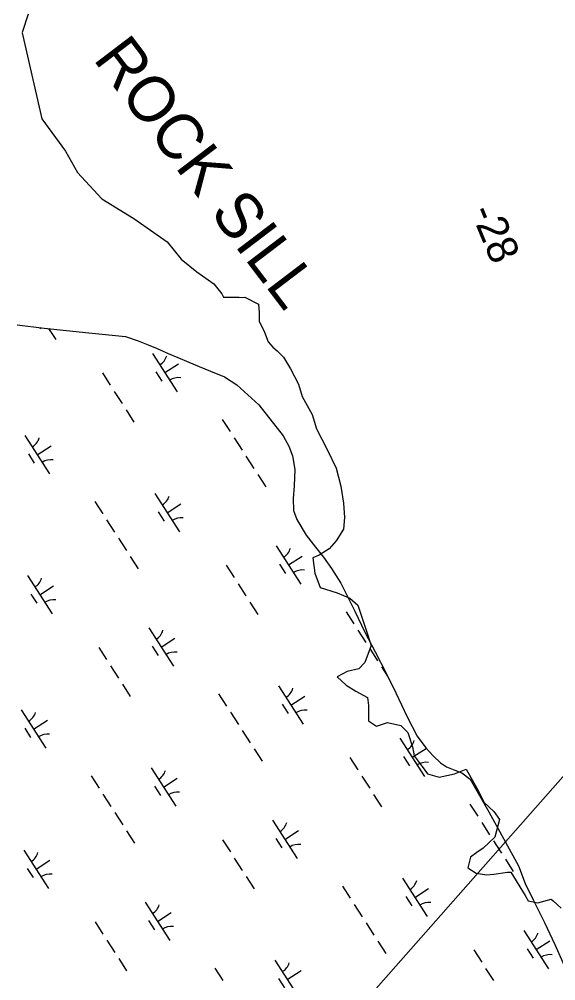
# Model space of a CAD drawing. Extents: x 3937982 to 3958556, y 219448 to 241894.
# Drawn here: x 3948736 to 3949325, y 226625 to 227680 of the extents above; entities that cross this region are included whole.
import ezdxf

# ---------------------------------------------------------------- set-up
doc = ezdxf.new("R2010")
doc.units = 0
for name, color, linetype in [('V-RIVR-EDGE', 7, 'Continuous'), ('V-RIVR-RANG', 7, 'Continuous'), ('V-RRAP-SILL-IDEN', 7, 'Continuous'), ('V-UTIL-LINE', 7, 'Continuous'), ('V-WETL-SWMP', 7, 'Continuous')]:
    doc.layers.add(name, color=color, linetype=linetype)

msp = doc.modelspace()

# ---------------------------------------------------------------- linework, layer by layer
at = {"layer": 'V-RIVR-EDGE'}
for points in [[(3948746.134, 227686.005), (3948739.531, 227665.724)], [(3948739.735, 227665.535), (3948761.326, 227571.012), (3948787.236, 227535.506), (3948800.191, 227511.995), (3948827.06, 227483.207), (3948862.087, 227461.615), (3948898.552, 227436.185), (3948913.906, 227416.993), (3948931.179, 227403.078), (3948949.892, 227390.124), (3948958.529, 227379.088), (3948960.448, 227375.249), (3948977.721, 227375.249)], [(3948976.723, 227375.027), (3948983.994, 227375.41), (3948998.738, 227367.546), (3948999.721, 227358.7), (3948999.721, 227348.871), (3949005.618, 227337.077), (3949009.55, 227326.265), (3949014.464, 227320.367), (3949019.379, 227316.436), (3949026.259, 227309.556), (3949034.122, 227296.778), (3949042.968, 227280.069), (3949046.9, 227266.308), (3949057.712, 227246.65), (3949062.626, 227230.924), (3949074.421, 227208.317), (3949084.25, 227187.676), (3949089.164, 227168.019), (3949092.113, 227149.344), (3949093.096, 227133.617), (3949092.113, 227120.84), (3949084.25, 227108.062), (3949076.387, 227099.216), (3949065.575, 227092.336), (3949058.695, 227089.387), (3949060.66, 227072.678), (3949066.558, 227056.951), (3949085.233, 227051.054), (3949098.993, 227045.157), (3949107.839, 227037.293), (3949117.668, 227007.807), (3949122.583, 226993.063), (3949115.703, 226974.388), (3949108.822, 226967.508), (3949096.045, 226964.559), (3949085.233, 226958.662), (3949095.062, 226949.816), (3949105.874, 226942.935), (3949118.651, 226936.055), (3949119.634, 226927.209), (3949119.634, 226923.277), (3949119.634, 226910.5), (3949128.48, 226904.602), (3949140.275, 226908.534), (3949155.018, 226905.585), (3949162.882, 226897.722), (3949167.796, 226881.996), (3949169.762, 226872.167), (3949178.608, 226860.372), (3949184.505, 226852.509), (3949197.283, 226848.577), (3949213.992, 226852.509), (3949226.77, 226857.423), (3949238.564, 226836.783), (3949246.428, 226821.056), (3949257.24, 226811.227), (3949263.137, 226802.381), (3949258.222, 226782.723), (3949245.445, 226770.929), (3949238.564, 226766.014), (3949231.684, 226761.1), (3949228.736, 226749.305), (3949237.582, 226743.408), (3949249.376, 226741.442), (3949257.24, 226742.425), (3949271.983, 226744.39), (3949275.915, 226744.39), (3949291.641, 226718.835), (3949294.59, 226712.938), (3949305.401, 226710.972), (3949320.145, 226714.904), (3949322.111, 226712.938), (3949330.957, 226705.075)]]:
    msp.add_lwpolyline(points, dxfattribs=at)
at = {"layer": 'V-UTIL-LINE'}
msp.add_line((3950898.169, 228625.327), (3949080.141, 226562.604), dxfattribs=at)
at = {"layer": 'V-WETL-SWMP'}
for p, q in [((3948734.219, 227345.065), (3948763.775, 227341.5)), ((3948758.696, 227342.113), (3948759.637, 227340.65)), ((3948763.775, 227341.5), (3948812.578, 227336.27)), ((3948768.598, 227340.983), (3948776.408, 227328.85)), ((3948812.578, 227336.27), (3948853.018, 227332.363)), ((3948853.018, 227332.363), (3948867.033, 227327.371)), ((3948867.033, 227327.371), (3948877.74, 227323.141)), ((3948877.74, 227323.141), (3948887.864, 227318.909)), ((3948887.864, 227318.909), (3948899.936, 227313.714)), ((3948882.475, 227313.595), (3948909.537, 227271.551)), ((3948899.936, 227313.714), (3948910.451, 227309.095)), ((3948910.451, 227309.095), (3948922.523, 227303.9)), ((3948896.006, 227292.573), (3948911.142, 227302.315)), ((3948922.523, 227303.9), (3948933.815, 227299.285)), ((3948933.815, 227299.285), (3948946.275, 227294.091)), ((3948946.275, 227294.091), (3948961.461, 227287.938)), ((3948827.609, 227292.197), (3948836.269, 227278.744)), ((3948886.271, 227293.442), (3948892.766, 227283.352)), ((3948961.461, 227287.938), (3948975.297, 227279.058)), ((3948975.297, 227279.058), (3948999.101, 227257.394)), ((3948840.599, 227272.017), (3948849.259, 227258.563)), ((3948853.589, 227251.836), (3948862.249, 227238.382)), ((3948999.101, 227257.394), (3949025.874, 227223.111)), ((3948959.176, 227241.309), (3948967.836, 227227.856)), ((3948742.608, 227223.565), (3948769.67, 227181.522)), ((3948972.166, 227221.129), (3948980.826, 227207.675)), ((3949025.874, 227223.111), (3949032.141, 227212.06)), ((3948756.139, 227202.543), (3948771.275, 227212.286)), ((3949032.141, 227212.06), (3949036.074, 227201.388)), ((3948746.404, 227203.413), (3948752.899, 227193.322)), ((3948985.156, 227200.948), (3948993.816, 227187.494)), ((3949036.074, 227201.388), (3949038.665, 227186.435)), ((3948998.146, 227180.767), (3949006.806, 227167.313)), ((3949038.665, 227186.435), (3949038.16, 227168.553)), ((3949038.16, 227168.553), (3949037.054, 227154.555)), ((3948885.174, 227159.875), (3948912.236, 227117.832)), ((3948819.309, 227151.28), (3948827.969, 227137.826)), ((3948898.705, 227138.853), (3948913.84, 227148.596)), ((3949037.054, 227154.555), (3949037.305, 227141.341)), ((3948888.97, 227139.722), (3948895.465, 227129.632)), ((3949037.305, 227141.341), (3949040.846, 227131.445)), ((3948832.299, 227131.099), (3948840.959, 227117.645)), ((3949040.846, 227131.445), (3949051.221, 227114.193)), ((3948845.289, 227110.918), (3948853.948, 227097.465)), ((3949051.221, 227114.193), (3949061.578, 227101.022)), ((3949018.303, 227102.576), (3949045.365, 227060.533)), ((3949061.578, 227101.022), (3949070.371, 227090.177)), ((3948858.278, 227090.738), (3948866.938, 227077.284)), ((3949031.834, 227081.555), (3949046.97, 227091.297)), ((3949070.371, 227090.177), (3949078.976, 227077.776)), ((3948963.437, 227081.179), (3948972.097, 227067.725)), ((3949022.099, 227082.424), (3949028.594, 227072.333)), ((3949078.976, 227077.776), (3949089.152, 227061.495)), ((3948745.306, 227069.845), (3948772.369, 227027.802)), ((3948758.838, 227048.824), (3948773.973, 227058.566)), ((3948976.427, 227060.998), (3948985.087, 227047.545)), ((3949089.152, 227061.495), (3949104.443, 227030.855)), ((3948749.102, 227049.693), (3948755.597, 227039.603)), ((3948989.417, 227040.818), (3948998.077, 227027.364)), ((3949095.004, 227030.291), (3949103.664, 227016.837)), ((3949104.443, 227030.855), (3949115.621, 227007.776)), ((3948878.436, 227012.547), (3948905.498, 226970.504)), ((3949107.994, 227010.11), (3949116.654, 226996.657)), ((3948891.967, 226991.525), (3948907.102, 227001.268)), ((3949115.621, 227007.776), (3949126.791, 226986.252)), ((3948823.57, 226991.15), (3948832.23, 226977.696)), ((3948882.232, 226992.394), (3948888.727, 226982.304)), ((3949120.984, 226989.93), (3949129.644, 226976.476)), ((3949126.791, 226986.252), (3949138.942, 226962.789)), ((3948836.56, 226970.969), (3948845.219, 226957.515)), ((3949133.974, 226969.749), (3949140.524, 226959.572)), ((3949138.942, 226962.789), (3949149.53, 226941.262)), ((3948849.549, 226950.788), (3948858.209, 226937.334)), ((3949021.002, 226948.857), (3949048.064, 226906.813)), ((3948955.137, 226940.262), (3948963.797, 226926.808)), ((3949034.533, 226927.835), (3949049.668, 226937.577)), ((3949149.53, 226941.262), (3949161.887, 226915.079)), ((3949024.798, 226928.704), (3949031.293, 226918.614)), ((3948738.568, 226922.517), (3948765.631, 226880.474)), ((3948968.126, 226920.081), (3948976.786, 226906.627)), ((3949161.887, 226915.079), (3949172.863, 226893.554)), ((3948752.1, 226901.496), (3948767.235, 226911.238)), ((3948742.364, 226902.365), (3948748.859, 226892.274)), ((3948981.116, 226899.9), (3948989.776, 226886.446)), ((3949172.863, 226893.554), (3949182.635, 226880.77)), ((3949154.131, 226891.558), (3949181.193, 226849.515)), ((3948994.106, 226879.719), (3949002.766, 226866.266)), ((3949167.662, 226870.536), (3949182.798, 226880.279)), ((3949182.635, 226880.77), (3949190.446, 226872.252)), ((3949190.446, 226872.252), (3949198.643, 226864.319)), ((3949099.265, 226870.161), (3949107.925, 226856.707)), ((3949157.927, 226871.406), (3949164.422, 226861.315)), ((3949198.643, 226864.319), (3949205.074, 226860.072)), ((3948881.134, 226858.827), (3948908.197, 226816.784)), ((3949205.074, 226860.072), (3949214.224, 226856.419)), ((3949214.224, 226856.419), (3949222.011, 226853.537)), ((3949222.011, 226853.537), (3949230.981, 226846.579)), ((3948815.269, 226850.232), (3948823.929, 226836.778)), ((3948894.665, 226837.805), (3948909.801, 226847.548)), ((3949112.255, 226849.98), (3949120.915, 226836.526)), ((3949230.981, 226846.579), (3949251.737, 226810.521)), ((3948828.259, 226830.051), (3948836.919, 226816.598)), ((3948884.93, 226838.675), (3948891.425, 226828.584)), ((3949125.245, 226829.799), (3949133.904, 226816.346)), ((3949230.832, 226819.273), (3949239.492, 226805.819)), ((3948841.249, 226809.871), (3948849.909, 226796.417)), ((3949251.737, 226810.521), (3949284.02, 226751.303)), ((3949014.264, 226801.528), (3949041.326, 226759.485)), ((3949243.822, 226799.092), (3949252.482, 226785.638)), ((3948854.239, 226789.69), (3948862.899, 226776.236)), ((3949027.795, 226780.507), (3949042.93, 226790.249)), ((3948959.397, 226780.131), (3948968.057, 226766.678)), ((3949018.06, 226781.376), (3949024.554, 226771.286)), ((3949256.811, 226778.911), (3949265.471, 226765.458)), ((3948741.267, 226768.798), (3948768.329, 226726.754)), ((3948754.798, 226747.776), (3948769.934, 226757.518)), ((3948972.387, 226759.951), (3948981.047, 226746.497)), ((3949269.801, 226758.731), (3949278.461, 226745.277)), ((3948745.063, 226748.645), (3948751.558, 226738.555)), ((3949284.02, 226751.303), (3949291.344, 226732.116)), ((3948985.377, 226739.77), (3948994.037, 226726.316)), ((3949156.829, 226737.838), (3949183.892, 226695.795)), ((3949090.964, 226729.243), (3949099.624, 226715.79)), ((3949170.361, 226716.817), (3949185.496, 226726.559)), ((3949291.344, 226732.116), (3949300.726, 226713.284)), ((3949160.625, 226717.686), (3949167.12, 226707.596)), ((3948874.396, 226711.499), (3948901.459, 226669.456)), ((3949103.954, 226709.063), (3949112.614, 226695.609)), ((3949300.726, 226713.284), (3949312.542, 226689.316)), ((3948887.927, 226690.477), (3948903.063, 226700.22)), ((3948819.53, 226690.102), (3948828.19, 226676.648)), ((3948878.192, 226691.347), (3948884.687, 226681.256)), ((3949116.944, 226688.882), (3949125.604, 226675.428)), ((3949312.542, 226689.316), (3949324.017, 226665.002)), ((3949289.959, 226680.54), (3949317.021, 226638.497)), ((3948832.52, 226669.921), (3948841.18, 226656.467)), ((3949129.934, 226668.701), (3949138.594, 226655.247)), ((3949303.49, 226659.518), (3949318.625, 226669.261)), ((3949324.017, 226665.002), (3949334.11, 226642.054)), ((3949235.093, 226659.143), (3949243.753, 226645.689)), ((3949293.755, 226660.387), (3949300.25, 226650.297)), ((3948845.51, 226649.74), (3948854.17, 226636.287)), ((3949016.962, 226647.809), (3949044.024, 226605.766)), ((3948951.097, 226639.214), (3948959.757, 226625.76)), ((3949030.493, 226626.787), (3949045.629, 226636.53)), ((3949248.082, 226638.962), (3949256.742, 226625.508)), ((3949020.758, 226627.656), (3949027.253, 226617.566))]:
    msp.add_line(p, q, dxfattribs=at)
for centre, start, end in [((3948881.256, 227315.927), 301.99668, 343.540338), ((3948911.156, 227269.476), 81.996677, 123.540335), ((3948741.389, 227225.898), 301.99668, 343.540338), ((3948771.289, 227179.446), 81.996677, 123.540335), ((3948883.954, 227162.208), 301.99668, 343.540338), ((3948913.855, 227115.756), 81.996677, 123.540335), ((3949017.084, 227104.909), 301.99668, 343.540338), ((3949046.984, 227058.457), 81.996677, 123.540335), ((3948744.087, 227072.178), 301.99668, 343.540338), ((3948773.987, 227025.726), 81.996677, 123.540335), ((3948877.216, 227014.88), 301.99668, 343.540338), ((3948907.116, 226968.428), 81.996677, 123.540335), ((3949019.782, 226951.189), 301.99668, 343.540338), ((3948737.349, 226924.85), 301.99668, 343.540338), ((3949049.682, 226904.738), 81.996677, 123.540335), ((3948767.249, 226878.398), 81.996677, 123.540335), ((3949152.912, 226893.891), 301.99668, 343.540338), ((3949182.812, 226847.439), 81.996677, 123.540335), ((3948879.915, 226861.16), 301.99668, 343.540338), ((3948909.815, 226814.708), 81.996677, 123.540335), ((3949013.044, 226803.861), 301.99668, 343.540338), ((3949042.944, 226757.409), 81.996677, 123.540335), ((3948740.048, 226771.13), 301.99668, 343.540338), ((3948769.948, 226724.679), 81.996677, 123.540335), ((3949155.61, 226740.171), 301.99668, 343.540338), ((3948873.177, 226713.832), 301.99668, 343.540338), ((3949185.51, 226693.719), 81.996677, 123.540335), ((3948903.077, 226667.38), 81.996677, 123.540335), ((3949288.739, 226682.873), 301.99668, 343.540338), ((3949318.639, 226636.421), 81.996677, 123.540335), ((3949015.743, 226650.142), 301.99668, 343.540338)]:
    msp.add_arc(centre, 17.623, start, end, dxfattribs=at)

# ---------------------------------------------------------------- texts
at = {"layer": 'V-RIVR-RANG'}
msp.add_text('-28', height=33.5, rotation=292.476833, dxfattribs=at).set_placement((3949231.083, 227469.448))
at = {"layer": 'V-RRAP-SILL-IDEN'}
msp.add_text('ROCK SILL', height=49.9999, rotation=307.247343, dxfattribs=at).set_placement((3948816.638, 227636.659))

doc.saveas('drawing.dxf')
